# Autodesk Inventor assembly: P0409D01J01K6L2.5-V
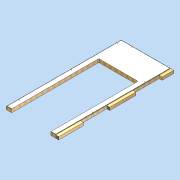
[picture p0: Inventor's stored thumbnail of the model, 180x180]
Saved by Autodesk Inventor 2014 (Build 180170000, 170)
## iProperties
Created: 2011-04
Part Number: P0409D01J01K6L2.5-V
Document SubType Name: Assembly
Designer: david.appleford
Description: 1w x 2.25w 01 Door Panel - 6 Locks 2.5 Lugs
Mass: 22000 g
Surface Area: 38005.8 cm^2
Volume: 103509 cm^3
Density: 0.212541 g/cm^3
Cost Center: £161.00
Justset: False
Title: 1w x 2.25w 01 Panel - 6 Locks 2.5 Lugs
Author: david.appleford
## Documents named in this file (5)
- C:\Documents and Settings\john.everitt\Local Settings\My Documents\Vault\Production MkII\Virtual Elements\Virtual Walls\Virtual Timber + MgO\P0409D01J01K6L2.5-V.iam
- C:\Documents and Settings\john.everitt\Local Settings\My Documents\Vault\Production MkII\VIRTUAL ELEMENTS\Virtual Lugs\Superceded Lugs\LA02C3V.ipt
- C:\Documents and Settings\john.everitt\Local Settings\My Documents\Vault\Production MkII\VIRTUAL ELEMENTS\Virtual Lugs\Superceded Lugs\LA02M3V.ipt
- C:\Documents and Settings\john.everitt\Local Settings\My Documents\Vault\Production MkII\VIRTUAL ELEMENTS\Virtual Lugs\Superceded Lugs\LA01C3V.ipt
- C:\Documents and Settings\john.everitt\Local Settings\My Documents\Vault\Production MkII\Virtual Elements\Virtual Walls\Virtual Timber + MgO\P0409D01J01K7-V.ipt
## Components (4 placed, 4 different names)
1. P0409D01J01K7-V:1 — Mate:1, Flush:1, Flush:2, Mate:7, Flush:11, Mate:14, Flush:12, Flush:13
2. LA02C3V:1 — Mate:1, Flush:1, Flush:2, Mate:9
3. LA02M3V:4 — Mate:7, Flush:11, Mate:9
4. LA01C3V:1 — Mate:14, Flush:12, Flush:13
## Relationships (9: Flush 5, Mate 4)
- Mate:1: P0409D01J01K7-V:1 ↔ LA02C3V:1
- Flush:1: P0409D01J01K7-V:1 ↔ LA02C3V:1
- Flush:2: P0409D01J01K7-V:1 ↔ LA02C3V:1
- Mate:7: P0409D01J01K7-V:1 ↔ LA02M3V:4
- Flush:11: P0409D01J01K7-V:1 ↔ LA02M3V:4
- Mate:9: LA02C3V:1 ↔ LA02M3V:4
- Mate:14: P0409D01J01K7-V:1 ↔ LA01C3V:1
- Flush:12: P0409D01J01K7-V:1 ↔ LA01C3V:1
- Flush:13: P0409D01J01K7-V:1 ↔ LA01C3V:1
## Named parameters: t = 1 mm, Cl = 2 mm
